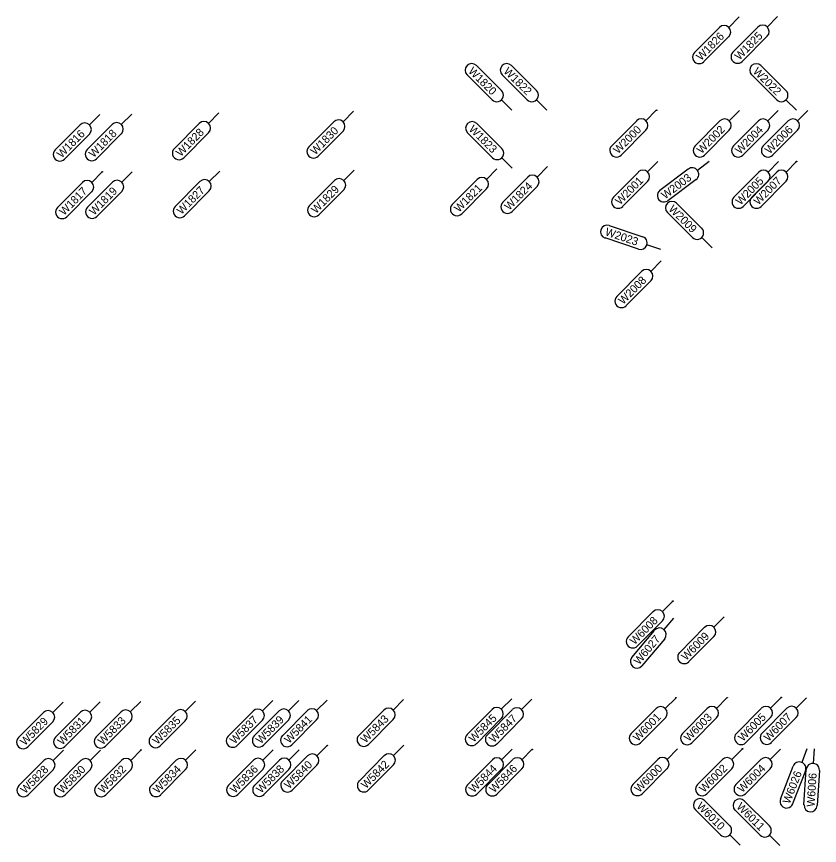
# Model space of a CAD drawing. Extents: x 12479652 to 12487250, y 9842710 to 9846560.
# Drawn here: x 12483100.8 to 12483226.2, y 9842733.8 to 9842863.3 of the extents above; entities that cross this region are included whole.
import ezdxf

# ---------------------------------------------------------------- set-up
doc = ezdxf.new("R2010")
doc.units = 0
doc.layers.add('_CIVIL_CONSTRUCTION', color=7, linetype='Continuous')
doc.layers.add('TextAlignmentLrg', color=7, linetype='Continuous')

msp = doc.modelspace()

# ---------------------------------------------------------------- linework, layer by layer
at = {"layer": '_CIVIL_CONSTRUCTION'}
for p, q in [((12483213.64, 9842863.29), (12483212.02, 9842861.66)), ((12483219.64, 9842863.34), (12483218.02, 9842861.71)), ((12483206.68, 9842857.74), (12483210.57, 9842861.66)), ((12483212.68, 9842857.8), (12483216.57, 9842861.71)), ((12483212.02, 9842860.21), (12483208.14, 9842856.3)), ((12483218.02, 9842860.26), (12483214.13, 9842856.35)), ((12483172.61, 9842855.7), (12483176.52, 9842851.81)), ((12483178.09, 9842855.7), (12483182, 9842851.81)), ((12483217.04, 9842855.68), (12483220.95, 9842851.79)), ((12483175.07, 9842850.35), (12483171.16, 9842854.24)), ((12483180.55, 9842850.35), (12483176.64, 9842854.24)), ((12483219.51, 9842850.33), (12483215.6, 9842854.22)), ((12483178.15, 9842848.74), (12483176.52, 9842850.36)), ((12483183.63, 9842848.73), (12483182, 9842850.36)), ((12483222.59, 9842848.72), (12483220.96, 9842850.34)), ((12483118.78, 9842848.12), (12483117.16, 9842846.49)), ((12483132.4, 9842848.28), (12483130.78, 9842846.65)), ((12483153.4, 9842848.54), (12483151.78, 9842846.91)), ((12483200.71, 9842848.7), (12483199.09, 9842847.07)), ((12483213.72, 9842848.69), (12483212.1, 9842847.06)), ((12483219.73, 9842848.69), (12483218.1, 9842847.06)), ((12483224.38, 9842848.69), (12483222.76, 9842847.06)), ((12483113.81, 9842848.06), (12483112.19, 9842846.43)), ((12483146.44, 9842842.99), (12483150.33, 9842846.9)), ((12483193.75, 9842843.15), (12483197.64, 9842847.06)), ((12483206.76, 9842843.14), (12483210.65, 9842847.06)), ((12483212.76, 9842843.14), (12483216.65, 9842847.05)), ((12483217.42, 9842843.14), (12483221.31, 9842847.05)), ((12483106.85, 9842842.51), (12483110.74, 9842846.42)), ((12483111.82, 9842842.57), (12483115.71, 9842846.48)), ((12483125.44, 9842842.73), (12483129.33, 9842846.65)), ((12483172.67, 9842846.64), (12483176.59, 9842842.75)), ((12483199.09, 9842845.61), (12483195.2, 9842841.7)), ((12483212.11, 9842845.61), (12483208.22, 9842841.7)), ((12483218.11, 9842845.61), (12483214.22, 9842841.69)), ((12483222.76, 9842845.61), (12483218.87, 9842841.69)), ((12483112.19, 9842844.97), (12483108.3, 9842841.06)), ((12483117.16, 9842845.03), (12483113.27, 9842841.12)), ((12483130.79, 9842845.2), (12483126.9, 9842841.29)), ((12483151.79, 9842845.46), (12483147.9, 9842841.54)), ((12483175.14, 9842841.3), (12483171.23, 9842845.19)), ((12483178.22, 9842839.68), (12483176.59, 9842841.3)), ((12483200.97, 9842840.7), (12483199.35, 9842839.07)), ((12483208.98, 9842840.7), (12483207.13, 9842839.32)), ((12483219.8, 9842840.69), (12483218.18, 9842839.06)), ((12483222.59, 9842840.69), (12483220.97, 9842839.06)), ((12483114.17, 9842839.07), (12483112.54, 9842837.44)), ((12483118.85, 9842839.11), (12483117.23, 9842837.48)), ((12483132.52, 9842839.21), (12483130.89, 9842837.58)), ((12483153.51, 9842839.37), (12483151.89, 9842837.74)), ((12483175.82, 9842839.54), (12483174.19, 9842837.91)), ((12483183.7, 9842839.9), (12483182.08, 9842838.27)), ((12483194.01, 9842835.15), (12483197.9, 9842839.06)), ((12483201.28, 9842836.22), (12483205.7, 9842839.53)), ((12483212.83, 9842835.14), (12483216.72, 9842839.05)), ((12483215.63, 9842835.14), (12483219.51, 9842839.05)), ((12483168.85, 9842833.99), (12483172.74, 9842837.9)), ((12483176.74, 9842834.35), (12483180.63, 9842838.26)), ((12483206.93, 9842837.88), (12483202.51, 9842834.58)), ((12483107.2, 9842833.52), (12483111.09, 9842837.44)), ((12483111.89, 9842833.56), (12483115.78, 9842837.47)), ((12483125.55, 9842833.66), (12483129.44, 9842837.57)), ((12483146.55, 9842833.82), (12483150.44, 9842837.73)), ((12483182.08, 9842836.82), (12483178.19, 9842832.9)), ((12483199.36, 9842837.61), (12483195.47, 9842833.7)), ((12483218.18, 9842837.61), (12483214.29, 9842833.69)), ((12483220.97, 9842837.61), (12483217.08, 9842833.69)), ((12483112.55, 9842835.99), (12483108.66, 9842832.08)), ((12483117.23, 9842836.03), (12483113.34, 9842832.11)), ((12483130.9, 9842836.13), (12483127.01, 9842832.22)), ((12483151.9, 9842836.29), (12483148.01, 9842832.37)), ((12483174.2, 9842836.45), (12483170.31, 9842832.54)), ((12483203.88, 9842834.17), (12483207.79, 9842830.28)), ((12483206.35, 9842828.82), (12483202.44, 9842832.71)), ((12483193.36, 9842830.7), (12483198.6, 9842828.95)), ((12483197.95, 9842827.01), (12483192.71, 9842828.75)), ((12483209.43, 9842827.21), (12483207.8, 9842828.83)), ((12483201.43, 9842826.93), (12483199.25, 9842827.66)), ((12483201.49, 9842825.17), (12483199.87, 9842823.54)), ((12483194.53, 9842819.62), (12483198.42, 9842823.54)), ((12483199.88, 9842822.09), (12483195.99, 9842818.18)), ((12483203.28, 9842772), (12483201.66, 9842770.37)), ((12483196.32, 9842766.45), (12483200.21, 9842770.37)), ((12483203.37, 9842769.33), (12483201.89, 9842767.57)), ((12483211.32, 9842769.55), (12483209.7, 9842767.92)), ((12483201.66, 9842768.92), (12483197.77, 9842765.01)), ((12483204.36, 9842764), (12483208.24, 9842767.92)), ((12483196.89, 9842763.22), (12483200.44, 9842767.45)), ((12483202.02, 9842766.13), (12483198.47, 9842761.9)), ((12483209.7, 9842766.47), (12483205.81, 9842762.56)), ((12483108.06, 9842756.25), (12483106.44, 9842754.62)), ((12483113.86, 9842756.29), (12483112.24, 9842754.66)), ((12483120.18, 9842756.34), (12483118.56, 9842754.71)), ((12483128.75, 9842756.4), (12483127.13, 9842754.77)), ((12483140.81, 9842756.48), (12483139.19, 9842754.85)), ((12483144.89, 9842756.51), (12483143.27, 9842754.88)), ((12483149.28, 9842756.54), (12483147.66, 9842754.91)), ((12483161.24, 9842756.62), (12483159.62, 9842754.99)), ((12483178.12, 9842756.74), (12483176.5, 9842755.11)), ((12483181.28, 9842756.69), (12483179.66, 9842755.06)), ((12483203.74, 9842756.87), (12483202.11, 9842755.24)), ((12483211.74, 9842756.88), (12483210.12, 9842755.25)), ((12483220.17, 9842756.9), (12483218.55, 9842755.27)), ((12483224.18, 9842756.91), (12483222.56, 9842755.28)), ((12483142.32, 9842750.99), (12483146.21, 9842754.9)), ((12483154.28, 9842751.07), (12483158.17, 9842754.99)), ((12483171.16, 9842751.19), (12483175.05, 9842755.1)), ((12483174.32, 9842751.14), (12483178.21, 9842755.05)), ((12483196.77, 9842751.32), (12483200.66, 9842755.23)), ((12483204.78, 9842751.34), (12483208.67, 9842755.25)), ((12483213.21, 9842751.35), (12483217.1, 9842755.26)), ((12483217.22, 9842751.36), (12483221.11, 9842755.27)), ((12483101.1, 9842750.7), (12483104.99, 9842754.62)), ((12483106.9, 9842750.74), (12483110.78, 9842754.66)), ((12483113.22, 9842750.79), (12483117.11, 9842754.7)), ((12483121.79, 9842750.85), (12483125.68, 9842754.76)), ((12483133.85, 9842750.93), (12483137.74, 9842754.84)), ((12483137.93, 9842750.96), (12483141.82, 9842754.87)), ((12483176.5, 9842753.66), (12483172.61, 9842749.74)), ((12483179.67, 9842753.61), (12483175.78, 9842749.69)), ((12483202.12, 9842753.79), (12483198.23, 9842749.87)), ((12483210.12, 9842753.8), (12483206.23, 9842749.89)), ((12483218.56, 9842753.82), (12483214.67, 9842749.91)), ((12483222.56, 9842753.83), (12483218.67, 9842749.91)), ((12483106.44, 9842753.17), (12483102.56, 9842749.26)), ((12483112.24, 9842753.21), (12483108.35, 9842749.3)), ((12483118.57, 9842753.25), (12483114.68, 9842749.34)), ((12483127.14, 9842753.31), (12483123.25, 9842749.4)), ((12483139.19, 9842753.4), (12483135.31, 9842749.49)), ((12483143.27, 9842753.43), (12483139.38, 9842749.51)), ((12483147.66, 9842753.46), (12483143.77, 9842749.54)), ((12483159.63, 9842753.54), (12483155.74, 9842749.63)), ((12483108.12, 9842748.73), (12483106.5, 9842747.1)), ((12483113.92, 9842748.75), (12483112.3, 9842747.11)), ((12483120.24, 9842748.76), (12483118.62, 9842747.13)), ((12483128.82, 9842748.77), (12483127.19, 9842747.14)), ((12483140.87, 9842748.8), (12483139.24, 9842747.17)), ((12483144.95, 9842748.8), (12483143.33, 9842747.17)), ((12483149.32, 9842749.48), (12483147.7, 9842747.85)), ((12483161.29, 9842749.5), (12483159.67, 9842747.87)), ((12483178.18, 9842748.87), (12483176.55, 9842747.24)), ((12483181.34, 9842748.87), (12483179.72, 9842747.24)), ((12483204, 9842748.92), (12483202.38, 9842747.29)), ((12483214.11, 9842748.89), (12483212.49, 9842747.26)), ((12483220.11, 9842748.9), (12483218.49, 9842747.27)), ((12483224.24, 9842748.96), (12483223.41, 9842746.81)), ((12483225.37, 9842748.96), (12483225.22, 9842746.66)), ((12483106.96, 9842743.2), (12483110.85, 9842747.11)), ((12483113.28, 9842743.21), (12483117.17, 9842747.12)), ((12483121.85, 9842743.23), (12483125.74, 9842747.14)), ((12483133.9, 9842743.25), (12483137.79, 9842747.16)), ((12483137.99, 9842743.26), (12483141.87, 9842747.17)), ((12483142.36, 9842743.93), (12483146.25, 9842747.84)), ((12483154.33, 9842743.95), (12483158.22, 9842747.87)), ((12483171.21, 9842743.32), (12483175.1, 9842747.23)), ((12483174.38, 9842743.33), (12483178.27, 9842747.24)), ((12483197.04, 9842743.37), (12483200.93, 9842747.28)), ((12483207.15, 9842743.34), (12483211.04, 9842747.25)), ((12483213.15, 9842743.35), (12483217.04, 9842747.26)), ((12483101.16, 9842743.19), (12483105.05, 9842747.1)), ((12483147.71, 9842746.4), (12483143.82, 9842742.48)), ((12483159.67, 9842746.42), (12483155.78, 9842742.51)), ((12483202.38, 9842745.84), (12483198.49, 9842741.92)), ((12483218.49, 9842745.82), (12483214.61, 9842741.91)), ((12483220.09, 9842741.08), (12483222.09, 9842746.23)), ((12483106.51, 9842745.65), (12483102.62, 9842741.74)), ((12483112.3, 9842745.66), (12483108.41, 9842741.75)), ((12483118.63, 9842745.68), (12483114.74, 9842741.76)), ((12483127.2, 9842745.69), (12483123.31, 9842741.78)), ((12483139.25, 9842745.71), (12483135.36, 9842741.8)), ((12483143.33, 9842745.72), (12483139.44, 9842741.81)), ((12483176.56, 9842745.79), (12483172.67, 9842741.87)), ((12483179.72, 9842745.79), (12483175.83, 9842741.88)), ((12483212.49, 9842745.81), (12483208.6, 9842741.89)), ((12483224, 9842745.48), (12483222, 9842740.34)), ((12483223.77, 9842740.2), (12483224.13, 9842745.71)), ((12483226.18, 9842745.57), (12483225.82, 9842740.07)), ((12483208.25, 9842740.85), (12483212.16, 9842736.96)), ((12483214.45, 9842740.81), (12483218.36, 9842736.92)), ((12483210.72, 9842735.51), (12483206.81, 9842739.4)), ((12483216.91, 9842735.46), (12483213, 9842739.35)), ((12483213.8, 9842733.89), (12483212.17, 9842735.51)), ((12483220, 9842733.84), (12483218.36, 9842735.47))]:
    msp.add_line(p, q, dxfattribs=at)
for centre, start, end in [((12483211.3, 9842860.93), 315.1702, 135.1702), ((12483217.3, 9842860.99), 315.1702, 135.1702), ((12483207.41, 9842857.02), 135.1702, 315.1702), ((12483213.41, 9842857.07), 135.1702, 315.1702), ((12483171.88, 9842854.97), 45.1702, 225.1702), ((12483177.36, 9842854.97), 45.1702, 225.1702), ((12483216.32, 9842854.95), 45.1702, 225.1702), ((12483175.79, 9842851.08), 225.1702, 45.1702), ((12483181.28, 9842851.08), 225.1702, 45.1702), ((12483220.23, 9842851.06), 225.1702, 45.1702), ((12483130.06, 9842845.92), 315.1702, 135.1702), ((12483151.06, 9842846.18), 315.1702, 135.1702), ((12483171.95, 9842845.91), 45.1702, 225.1702), ((12483198.36, 9842846.34), 315.1702, 135.1702), ((12483211.38, 9842846.33), 315.1702, 135.1702), ((12483217.38, 9842846.33), 315.1702, 135.1702), ((12483222.04, 9842846.33), 315.1702, 135.1702), ((12483111.46, 9842845.7), 315.1702, 135.1702), ((12483116.44, 9842845.76), 315.1702, 135.1702), ((12483147.17, 9842842.27), 135.1702, 315.1702), ((12483194.47, 9842842.42), 135.1702, 315.1702), ((12483207.49, 9842842.42), 135.1702, 315.1702), ((12483213.49, 9842842.42), 135.1702, 315.1702), ((12483218.15, 9842842.42), 135.1702, 315.1702), ((12483107.57, 9842841.78), 135.1702, 315.1702), ((12483112.55, 9842841.85), 135.1702, 315.1702), ((12483126.17, 9842842.01), 135.1702, 315.1702), ((12483175.86, 9842842.02), 225.1702, 45.1702), ((12483198.63, 9842838.34), 315.1702, 135.1702), ((12483206.31, 9842838.7), 306.762, 126.762), ((12483217.45, 9842838.33), 315.1702, 135.1702), ((12483220.24, 9842838.33), 315.1702, 135.1702), ((12483116.5, 9842836.75), 315.1702, 135.1702), ((12483130.17, 9842836.85), 315.1702, 135.1702), ((12483151.17, 9842837.01), 315.1702, 135.1702), ((12483173.47, 9842837.18), 315.1702, 135.1702), ((12483181.36, 9842837.54), 315.1702, 135.1702), ((12483111.82, 9842836.71), 315.1702, 135.1702), ((12483201.89, 9842835.4), 126.762, 306.762), ((12483169.58, 9842833.26), 135.1702, 315.1702), ((12483177.47, 9842833.63), 135.1702, 315.1702), ((12483194.74, 9842834.42), 135.1702, 315.1702), ((12483203.16, 9842833.44), 45.1702, 225.1702), ((12483213.56, 9842834.42), 135.1702, 315.1702), ((12483216.35, 9842834.42), 135.1702, 315.1702), ((12483107.93, 9842832.8), 135.1702, 315.1702), ((12483112.61, 9842832.84), 135.1702, 315.1702), ((12483126.28, 9842832.94), 135.1702, 315.1702), ((12483147.28, 9842833.1), 135.1702, 315.1702), ((12483193.04, 9842829.72), 71.5941, 251.5941), ((12483207.07, 9842829.55), 225.1702, 45.1702), ((12483198.27, 9842827.98), 251.5941, 71.5941), ((12483199.15, 9842822.81), 315.1702, 135.1702), ((12483195.26, 9842818.9), 135.1702, 315.1702), ((12483200.94, 9842769.64), 315.1702, 135.1702), ((12483208.97, 9842767.19), 315.1702, 135.1702), ((12483201.23, 9842766.79), 319.9516, 139.9516), ((12483197.05, 9842765.73), 135.1702, 315.1702), ((12483205.08, 9842763.28), 135.1702, 315.1702), ((12483197.68, 9842762.56), 139.9516, 319.9516), ((12483105.72, 9842753.89), 315.1702, 135.1702), ((12483111.51, 9842753.93), 315.1702, 135.1702), ((12483117.84, 9842753.98), 315.1702, 135.1702), ((12483126.41, 9842754.04), 315.1702, 135.1702), ((12483138.47, 9842754.12), 315.1702, 135.1702), ((12483142.54, 9842754.15), 315.1702, 135.1702), ((12483146.93, 9842754.18), 315.1702, 135.1702), ((12483158.9, 9842754.26), 315.1702, 135.1702), ((12483175.78, 9842754.38), 315.1702, 135.1702), ((12483178.94, 9842754.33), 315.1702, 135.1702), ((12483201.39, 9842754.51), 315.1702, 135.1702), ((12483209.39, 9842754.53), 315.1702, 135.1702), ((12483217.83, 9842754.54), 315.1702, 135.1702), ((12483221.84, 9842754.55), 315.1702, 135.1702), ((12483143.04, 9842750.27), 135.1702, 315.1702), ((12483155.01, 9842750.35), 135.1702, 315.1702), ((12483171.89, 9842750.47), 135.1702, 315.1702), ((12483175.05, 9842750.42), 135.1702, 315.1702), ((12483197.5, 9842750.6), 135.1702, 315.1702), ((12483205.51, 9842750.61), 135.1702, 315.1702), ((12483213.94, 9842750.63), 135.1702, 315.1702), ((12483217.95, 9842750.64), 135.1702, 315.1702), ((12483101.83, 9842749.98), 135.1702, 315.1702), ((12483107.62, 9842750.02), 135.1702, 315.1702), ((12483113.95, 9842750.07), 135.1702, 315.1702), ((12483122.52, 9842750.12), 135.1702, 315.1702), ((12483134.58, 9842750.21), 135.1702, 315.1702), ((12483138.65, 9842750.24), 135.1702, 315.1702), ((12483105.78, 9842746.38), 315.1702, 135.1702), ((12483111.57, 9842746.39), 315.1702, 135.1702), ((12483117.9, 9842746.4), 315.1702, 135.1702), ((12483126.47, 9842746.42), 315.1702, 135.1702), ((12483138.52, 9842746.44), 315.1702, 135.1702), ((12483142.6, 9842746.45), 315.1702, 135.1702), ((12483146.98, 9842747.12), 315.1702, 135.1702), ((12483158.94, 9842747.14), 315.1702, 135.1702), ((12483175.83, 9842746.51), 315.1702, 135.1702), ((12483178.99, 9842746.52), 315.1702, 135.1702), ((12483201.66, 9842746.56), 315.1702, 135.1702), ((12483211.77, 9842746.53), 315.1702, 135.1702), ((12483217.77, 9842746.54), 315.1702, 135.1702), ((12483223.04, 9842745.86), 338.8072, 158.8072), ((12483225.15, 9842745.64), 356.3067, 176.3067), ((12483122.58, 9842742.5), 135.1702, 315.1702), ((12483134.63, 9842742.53), 135.1702, 315.1702), ((12483138.71, 9842742.53), 135.1702, 315.1702), ((12483143.09, 9842743.21), 135.1702, 315.1702), ((12483155.05, 9842743.23), 135.1702, 315.1702), ((12483171.94, 9842742.6), 135.1702, 315.1702), ((12483175.1, 9842742.6), 135.1702, 315.1702), ((12483197.77, 9842742.65), 135.1702, 315.1702), ((12483207.88, 9842742.62), 135.1702, 315.1702), ((12483213.88, 9842742.63), 135.1702, 315.1702), ((12483101.89, 9842742.46), 135.1702, 315.1702), ((12483107.68, 9842742.47), 135.1702, 315.1702), ((12483114.01, 9842742.49), 135.1702, 315.1702), ((12483207.53, 9842740.13), 45.1702, 225.1702), ((12483213.72, 9842740.08), 45.1702, 225.1702), ((12483221.05, 9842740.71), 158.8072, 338.8072), ((12483224.8, 9842740.13), 176.3067, 356.3067), ((12483211.44, 9842736.24), 225.1702, 45.1702), ((12483217.64, 9842736.19), 225.1702, 45.1702)]:
    msp.add_arc(centre, 1.03, start, end, dxfattribs=at)
at = {"layer": 'TextAlignmentLrg'}
for centre in [(12483200.77, 9842848.71), (12483222.6, 9842840.7), (12483114.19, 9842839.09), (12483203.28, 9842772), (12483203.78, 9842756.92), (12483211.79, 9842756.93), (12483220.22, 9842756.95), (12483120.24, 9842748.76), (12483149.33, 9842749.48), (12483181.34, 9842748.84), (12483214.16, 9842748.94)]:
    msp.add_circle(centre, 0.05, dxfattribs=at)

# ---------------------------------------------------------------- texts
at = {"layer": '_CIVIL_CONSTRUCTION'}
for s, rotation, p in [('W1826', 45.1702, (12483207.68, 9842856.39)), ('W1825', 45.1702, (12483213.69, 9842856.46)), ('W1820', 315.1702, (12483171.25, 9842854.7)), ('W1822', 315.1702, (12483176.76, 9842854.68)), ('W2022', 315.1702, (12483215.71, 9842854.66)), ('W1816', 45.1702, (12483107.84, 9842841.15)), ('W1818', 45.1702, (12483112.82, 9842841.22)), ('W1828', 45.1702, (12483126.44, 9842841.38)), ('W1830', 45.1702, (12483147.44, 9842841.64)), ('W1823', 315.1702, (12483171.33, 9842845.64)), ('W2000', 45.1702, (12483194.74, 9842841.8)), ('W2002', 45.1702, (12483207.78, 9842841.81)), ('W2004', 45.1702, (12483213.76, 9842841.78)), ('W2006', 45.1702, (12483218.42, 9842841.79)), ('W2001', 45.1702, (12483195.05, 9842833.83)), ('W2003', 36.762, (12483202.08, 9842834.75)), ('W2005', 45.1702, (12483213.85, 9842833.8)), ('W2007', 45.1702, (12483216.64, 9842833.8)), ('W1817', 45.1702, (12483108.21, 9842832.18)), ('W1819', 45.1702, (12483112.89, 9842832.21)), ('W1827', 45.1702, (12483126.56, 9842832.32)), ('W1829', 45.1702, (12483147.55, 9842832.47)), ('W1821', 45.1702, (12483169.89, 9842832.67)), ('W1824', 45.1702, (12483177.73, 9842832.99)), ('W2009', 315.1702, (12483202.53, 9842833.17)), ('W2023', 341.5941, (12483192.61, 9842829.2)), ('W2008', 45.1702, (12483195.53, 9842818.27)), ('W6008', 45.1702, (12483197.32, 9842765.1)), ('W6027', 49.9516, (12483198.01, 9842761.97)), ('W6009', 45.1702, (12483205.36, 9842762.65)), ('W5829', 45.1702, (12483102.1, 9842749.35)), ('W5831', 45.1702, (12483107.93, 9842749.43)), ('W5833', 45.1702, (12483114.23, 9842749.45)), ('W5835', 45.1702, (12483122.8, 9842749.51)), ('W5837', 45.1702, (12483134.86, 9842749.59)), ('W5839', 45.1702, (12483138.93, 9842749.61)), ('W5841', 45.1702, (12483143.35, 9842749.68)), ('W5843', 45.1702, (12483155.29, 9842749.73)), ('W5845', 45.1702, (12483172.17, 9842749.85)), ('W5847', 45.1702, (12483175.33, 9842749.8)), ('W6001', 45.1702, (12483197.81, 9842750.01)), ('W6003', 45.1702, (12483205.78, 9842749.99)), ('W6005', 45.1702, (12483214.22, 9842750.01)), ('W6007', 45.1702, (12483218.23, 9842750.02)), ('W5828', 45.1702, (12483102.16, 9842741.84)), ('W5830', 45.1702, (12483107.95, 9842741.85)), ('W5832', 45.1702, (12483114.3, 9842741.88)), ('W5834', 45.1702, (12483122.85, 9842741.87)), ('W5836', 45.1702, (12483134.9, 9842741.89)), ('W5838', 45.1702, (12483138.98, 9842741.91)), ('W5840', 45.1702, (12483143.36, 9842742.58)), ('W5842', 45.1702, (12483155.35, 9842742.62)), ('W5844', 45.1702, (12483172.21, 9842741.96)), ('W5846', 45.1702, (12483175.37, 9842741.97)), ('W6000', 45.1702, (12483198.04, 9842742.02)), ('W6002', 45.1702, (12483208.17, 9842742.01)), ('W6004', 45.1702, (12483214.14, 9842741.99)), ('W6026', 68.8072, (12483221.55, 9842740.24)), ('W6006', 86.3067, (12483225.42, 9842739.84)), ('W6010', 315.1702, (12483206.9, 9842739.86)), ('W6011', 315.1702, (12483213.13, 9842739.77))]:
    msp.add_text(s, height=1.25, rotation=rotation, dxfattribs=at).set_placement(p)

doc.saveas('drawing.dxf')
